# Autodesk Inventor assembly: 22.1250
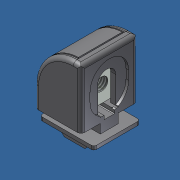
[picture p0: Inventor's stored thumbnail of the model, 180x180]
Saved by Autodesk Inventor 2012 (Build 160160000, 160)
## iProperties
Created: 2016-06
Part Number: 22.1250
Document SubType Name: Assembly
Designer: Admin
Description: SCREW BLOCK 30
Author: Admin
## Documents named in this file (4)
- C:\Andys Backup Data\ANDY'S INVENTOR\INVENTOR LIBRARIES\PARTS LIBRARY\30 SERIES\22.1250_SCREW_BLOCK_30.iam
- C:\Andys Backup Data\ANDY'S INVENTOR\INVENTOR LIBRARIES\PARTS LIBRARY\30 SERIES\SUBCOMPONENTS\22.1250_SCREW_BLOCK_30_BODY.ipt
- C:\Andys Backup Data\ANDY'S INVENTOR\INVENTOR LIBRARIES\PARTS LIBRARY\30 SERIES\SUBCOMPONENTS\SCREW BLOCK M6 NUT.ipt
- C:\Andys Backup Data\ANDY'S INVENTOR\INVENTOR LIBRARIES\PARTS LIBRARY\30 SERIES\SUBCOMPONENTS\SCREW BLOCK COVER.ipt
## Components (3 placed, 3 different names)
1. 22.1250_SCREW_BLOCK_30_BODY:1 — Mate:1, Mate:3, Mate:4, Mate:5, Mate:6
2. SCREW BLOCK M6 NUT:1 — Mate:1, Mate:2, Mate:3
3. SCREW BLOCK COVER:1 — Mate:4, Mate:5, Mate:6
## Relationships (6: Mate 6)
- Mate:1: 22.1250_SCREW_BLOCK_30_BODY:1 ↔ SCREW BLOCK M6 NUT:1
- Mate:2: SCREW BLOCK M6 NUT:1
- Mate:3: 22.1250_SCREW_BLOCK_30_BODY:1 ↔ SCREW BLOCK M6 NUT:1
- Mate:4: 22.1250_SCREW_BLOCK_30_BODY:1 ↔ SCREW BLOCK COVER:1
- Mate:5: 22.1250_SCREW_BLOCK_30_BODY:1 ↔ SCREW BLOCK COVER:1
- Mate:6: 22.1250_SCREW_BLOCK_30_BODY:1 ↔ SCREW BLOCK COVER:1
